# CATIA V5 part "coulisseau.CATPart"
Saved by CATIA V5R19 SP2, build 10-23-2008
Part number: coulisseau
Bounding box of the stored display mesh (mm): x 0 to 50, y 0 to 20, z 0 to 20
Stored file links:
  C:\Users\Guillaume\Desktop\ETUDES\IFMA\S3\IAO\Projet IAO\ggaubert_1504\coulisseau.CATPart
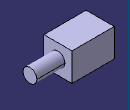
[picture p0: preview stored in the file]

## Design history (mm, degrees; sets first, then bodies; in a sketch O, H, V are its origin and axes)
Body1 (main body)
  Sketch1 on yz-plane, origin (0, 0, 0), H (0, 1, 0), V (0, 0, 1)
    line L1 (0, 20) -> (20, 20)
    line L2 (20, 20) -> (20, 0)
    line L3 (20, 0) -> (0, 0)
    line L4 (0, 0) -> (0, 20)
    point P4 (0, 0)
    length L3 = 20
    distance L1 L3 = 20
    horizontal: L1 H, L3 H
    vertical: L2 V, L4 V
    coincidence: P4 O
  Pad1: profile Sketch1, direction (1, 0, 0), length 30
  Sketch2 on end face of Pad1, origin (30, 0, 0), H (0, 1, 0), V (0, 0, 1)
    circle A1 centre (10, 10) radius 5
    point P1 (10, 10)
    reference projected line E1 (20, 0) -> (20, 29.9074) from edge [face of Pad1 from Sketch1.L2 | end face of Pad1]
    reference projected line E2 (0, 29.9074) -> (0, 0) from edge [face of Pad1 from Sketch1.L4 | end face of Pad1]
    reference projected line E3 (0, 0) -> (58.9939, 0) from edge [face of Pad1 from Sketch1.L3 | end face of Pad1]
    reference projected line E4 (58.9939, 20) -> (0, 20) from edge [face of Pad1 from Sketch1.L1 | end face of Pad1]
    radius A1 = 5
    equidistance: E1 E2 P1, E3 E4 P1
  Pad2: profile Sketch2, direction (1, 0, 0), length 20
